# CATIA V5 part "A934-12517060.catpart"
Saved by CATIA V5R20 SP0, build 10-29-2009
Part number: A934-12517060
Source: Unknown
Property "A": "85.000"
Property "ARTICLENO": "A934-12517060"
Property "B": "30.000"
Property "BOMINFO": "A934-12517060"
Property "CODE": "A934-12517060"
Property "L": "170.000"
Property "L1": "127.860"
Property "LINA": "A934-12517060"
Property "NB": "A934-12517060"
Property "NBSYN": "$CODE."
Property "NN": "A934"
Property "NT": "VDI 3357 H-Type Cam Drivers, self-lubricating"
Property "SUPPLIER": "CF"
Property "T": "60.000"
Property "W": "125.000"
Bounding box of the stored display mesh (mm): x 0 to 170, y 0 to 60, z -125 to 0
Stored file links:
  C:\Users\Utente\Desktop\3D files A934\A934-12517060.catpart
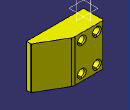
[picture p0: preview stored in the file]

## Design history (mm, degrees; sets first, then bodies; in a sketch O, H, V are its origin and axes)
Body1 "Geometry.1" (main body)
  Solid1 "A934-12517060.catpart": solid without history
